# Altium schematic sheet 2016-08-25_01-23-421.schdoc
size 213 x 130 mm; SheetNumber: 1; SheetTotal: 1
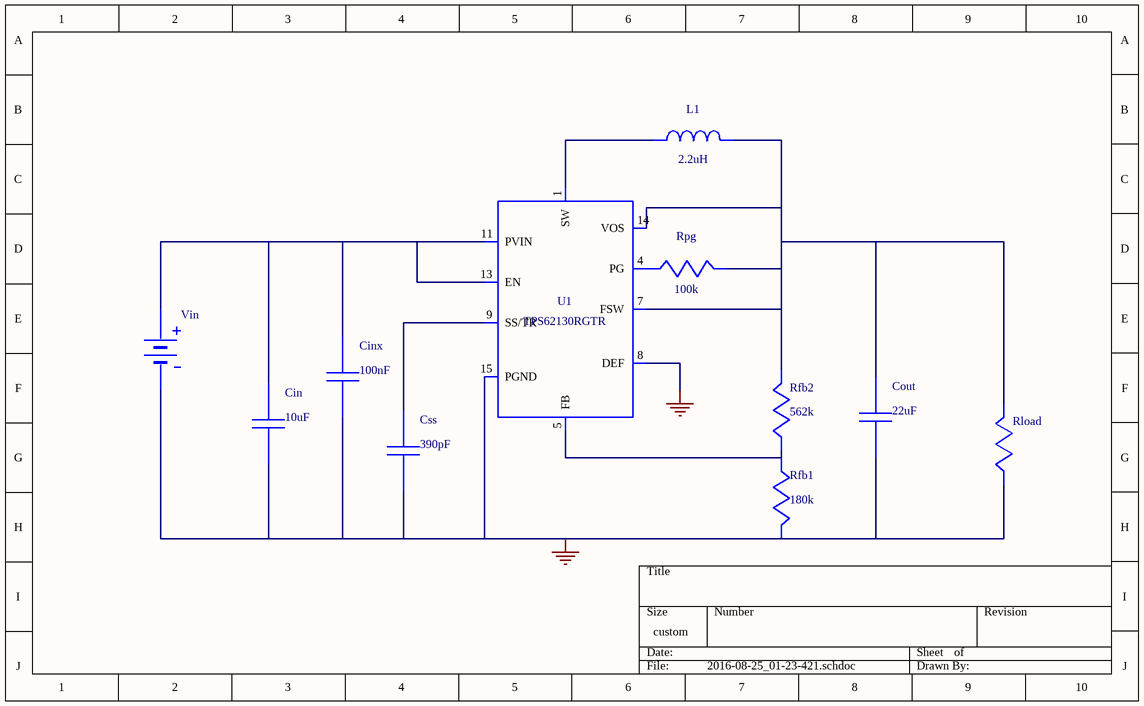
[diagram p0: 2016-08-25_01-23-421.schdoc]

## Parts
Cin  value 10uF  (hidden comment: TMK316BJ106KL-T)
Cinx  value 100nF  (hidden comment: C0603C104K3RACTU)
Cout  value 22uF  (hidden comment: GRM21BR60J226ME39L)
Css  value 390pF  (hidden comment: CC0805KRX7R9BB391)
L1  value 2.2uH  (hidden comment: SRN8040-2R2Y)
Rfb1  value 180k  (hidden comment: RC0603FR-07180KL)
Rfb2  value 562k  (hidden comment: CRCW0402562KFKED)
Rload  WB_LOAD_RESISTOR  (value not drawn)
Rpg  value 100k  (hidden comment: CRCW0402100KFKED)
U1  TPS62130RGTR
Vin  WB_BATTERY  (value not drawn)

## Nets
0: Cin.2 Cinx.2 Cout.2 Css.2 Rfb1.1 Rload.2 U1.6(AGND) U1.8(DEF) U1.15(PGND) U1.16(PGND) U1.17(ETPAD) Vin.2(-)
NetCin_1: Cin.1 Cinx.1 U1.10(AVIN) U1.11(PVIN) U1.12(PVIN) U1.13(EN) Vin.1(+)
NetCout_1: Cout.1 L1.2 Rfb2.1 Rload.1 Rpg.1 U1.7(FSW) U1.14(VOS)
NetCss_1: Css.1 U1.9(SS/TR)
NetL1_1: L1.1 U1.1(SW) U1.2(SW) U1.3(SW)
NetRfb1_2: Rfb1.2 Rfb2.2 U1.5(FB)
NetRpg_2: Rpg.2 U1.4(PG)

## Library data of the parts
Cin = TMK316BJ106KL-T: Manufacturer Name: Taiyo Yuden
Cinx = C0603C104K3RACTU: Manufacturer Name: Kemet
Cout = GRM21BR60J226ME39L: GRM21BR60J226ME3; Manufacturer Name: MuRata
Css = CC0805KRX7R9BB391: CC0805KRX7R9BB39; Manufacturer Name: Yageo America
L1 = SRN8040-2R2Y: Manufacturer Name: Bourns
Rfb1 = RC0603FR-07180KL: Manufacturer Name: Yageo America
Rfb2 = CRCW0402562KFKED: Manufacturer Name: Vishay-Dale
Rpg = CRCW0402100KFKED: Manufacturer Name: Vishay-Dale
U1 = TPS62130RGTR: Manufacturer Name: Texas Instruments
